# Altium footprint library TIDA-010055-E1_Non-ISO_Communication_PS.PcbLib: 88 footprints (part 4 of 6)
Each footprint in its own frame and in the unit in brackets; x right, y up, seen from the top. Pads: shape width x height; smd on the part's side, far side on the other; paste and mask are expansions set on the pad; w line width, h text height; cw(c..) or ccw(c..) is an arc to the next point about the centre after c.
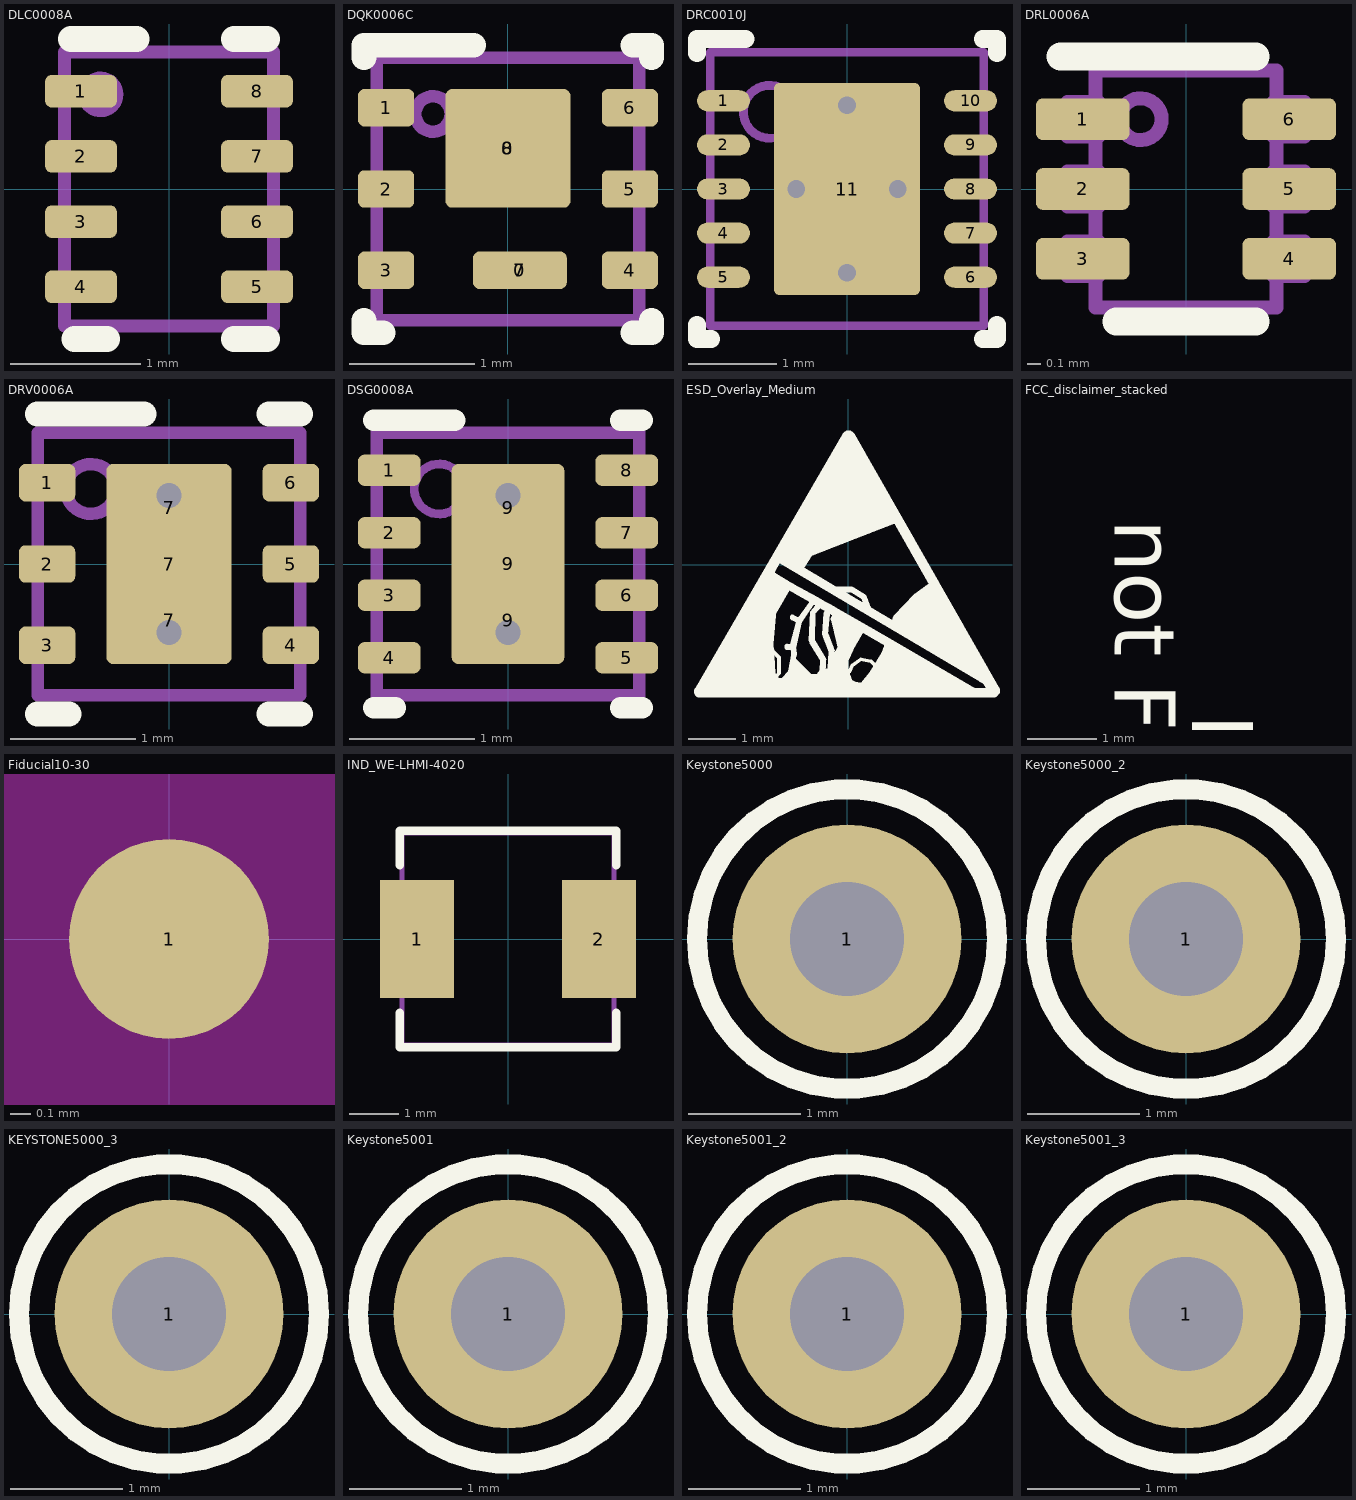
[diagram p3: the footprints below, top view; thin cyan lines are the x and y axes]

## DLC0008A [mm] "QFN-8 (2.0mmX1.5mm)"
height 1
pads (8):
  rrect40% 0.55x0.25 smd: 1(-0.675,0.75) 2(-0.675,0.25) 3(-0.675,-0.25) 4(-0.675,-0.75) 5(0.675,-0.75) 6(0.675,-0.25) 7(0.675,0.25) 8(0.675,0.75)
Top Overlay:
  lines w0.2: -0.75,1.15 -0.25,1.15 ; -0.725,-1.15 -0.475,-1.15 ; 0.5,-1.15 0.75,-1.15 ; 0.5,1.15 0.75,1.15
Mechanical 5:
  circle w0.1: c-0.525,0.725 r0.125
  lines w0.1: -0.8,-1.05 -0.8,1.05 0.8,1.05 0.8,-1.05 -0.8,-1.05
  text ".Designator" at 0.702,-3.338 h0.64
3D body: height 1, standoff 0, extent -0.799,-1.049 0.799,1.049
3D body: height 1.02, standoff 0.5, extent -0.549,0.601 -0.301,0.849

## DQK0006C [mm] "WSON"
height 0.8
pads (10):
  rrect50% 0.9x0.86 on Top Paste: 0(0,0.325)
  rrect50% 0.7x0.29 on Top Paste: 0(0.095,-0.65)
  rrect33% 0.45x0.3 smd: 1(-0.975,0.65) 2(-0.975,0) 3(-0.975,-0.65) 4(0.975,-0.65) 5(0.975,0) 6(0.975,0.65)
  rrect33% 0.75x0.3 smd paste-0.15: 7(0.095,-0.65)
  rrect11% 1x0.95 smd paste-0.5: 8(0,0.325)
Top Overlay:
  lines w0.2: -1.15,-1.05 -1.15,-1.15 -1,-1.15 ; -1.15,1.05 -1.15,1.15 -0.275,1.15 ; 1,-1.15 1.15,-1.15 1.15,-1.05 ; 1,1.15 1.15,1.15 1.15,1.05
Mechanical 5:
  circle w0.1: c-0.6,0.6 r0.141
  lines w0.1: -1.05,-1.05 1.05,-1.05 1.05,1.05 -1.05,1.05 -1.05,-1.05
  text ".Designator" at -0.524,-0.406 h0.64
3D body "DQK0006C.stp": height 0.82, standoff 0, extent -1,-1 1,1

## DRC0010J [mm] "SON, 10-Leads, Body 3x3mm, Pitch 0.5mm, Thermal Pad 2.4x1.65mm, TI Recommended"
height 1
pads (11):
  rrect100% 0.6x0.24 smd: 1(-1.4,1) 2(-1.4,0.5) 3(-1.4,0) 4(-1.4,-0.5) 5(-1.4,-1) 6(1.4,-1) 7(1.4,-0.5) 8(1.4,0) 9(1.4,0.5) 10(1.4,1)
  rrect6% 1.65x2.4 smd paste-0.825: 11(0,0)
via 0,-0.95 diameter 0.5 hole 0.2
via -0.575,0 diameter 0.5 hole 0.2
via 0,0.95 diameter 0.5 hole 0.2
via 0.575,0 diameter 0.5 hole 0.2
Top Overlay:
  lines w0.2: -1.7,-1.54 -1.7,-1.7 -1.54,-1.7 ; -1.7,1.54 -1.7,1.7 -1.15,1.7 ; 1.54,-1.7 1.7,-1.7 1.7,-1.54 ; 1.54,1.7 1.7,1.7 1.7,1.54
Top Paste:
  rectangle: -0.75,-1.16 0.75,-0.1
  rectangle: -0.75,0.1 0.75,1.16
Mechanical 5:
  circle w0.1: c-0.875,0.875 r0.3
  lines w0.1: -1.55,-1.55 -1.55,1.55 1.55,1.55 1.55,-1.55 -1.55,-1.55
  text ".Designator" at 0.129,0.544 h0.64
3D body "DRC0010J.stp": height 0.77, standoff 0, extent -1.5,-1.5 1.5,1.5

## DRL0006A [mm] "SOTFL, 6-Flat Leads, Body 1.2x1.6x0.6mm, Pitch 0.5mm, TI recommended"
height 0.6
pads (6):
  rrect33% 0.67x0.3 smd: 1(-0.74,0.5) 2(-0.74,0) 3(-0.74,-0.5) 4(0.74,-0.5) 5(0.74,0) 6(0.74,0.5)
Top Overlay:
  lines w0.2: -0.9,0.95 0.5,0.95 ; -0.5,-0.95 0.5,-0.95
Mechanical 5:
  circle w0.1: c-0.325,0.5 r0.15
  lines w0.1: -0.65,-0.625 -0.65,-0.85 0.65,-0.85 0.65,-0.625 ; -0.65,-0.375 -0.65,-0.125 ; -0.65,0.125 -0.65,0.375 ; -0.65,0.625 -0.65,0.85 0.65,0.85 0.65,0.625 ; 0.65,-0.375 0.65,0.375 ; -0.85,-0.625 -0.627,-0.625 -0.627,-0.375 -0.85,-0.375 -0.85,-0.625 ; -0.85,-0.125 -0.85,0.125 -0.627,0.125 -0.627,-0.125 -0.85,-0.125 ; -0.85,0.375 -0.627,0.375 -0.627,0.625 -0.85,0.625 -0.85,0.375 ; 0.627,-0.625 0.85,-0.625 0.85,-0.375 0.627,-0.375 0.627,-0.625 ; 0.627,-0.125 0.627,0.125 0.85,0.125 0.85,-0.125 0.627,-0.125 ; 0.627,0.375 0.85,0.375 0.85,0.625 0.627,0.625 0.627,0.375
  text ".Designator" at -0.825,1.112 h0.64
3D body "DRL0006A.stp": height 0.61, standoff 0.01, extent -0.8,-0.8 0.8,0.8

## DRV0006A [mm] "SON, 6-Leads, Body 2x2mm, Pitch 0.65mm, Thermal Pad 1.6x1mm, TI Recommended"
height 0.8
pads (9):
  rrect33% 0.45x0.3 smd: 1(-0.975,0.65) 2(-0.975,0) 3(-0.975,-0.65) 4(0.975,-0.65) 5(0.975,0) 6(0.975,0.65)
  rrect50% 1x0.7 on Top Paste: 7(0,-0.45) 7(0,0.45)
  rrect10% 1x1.6 smd paste-0.5: 7(0,0)
via 0,-0.55 diameter 0.5 hole 0.2
via 0,0.55 diameter 0.5 hole 0.2
Top Overlay:
  lines w0.2: -1.05,-1.2 -0.8,-1.2 ; -1.05,1.2 -0.2,1.2 ; 0.8,-1.2 1.05,-1.2 ; 0.8,1.2 1.05,1.2
Mechanical 5:
  circle w0.1: c-0.625,0.6 r0.2
  lines w0.1: -1.05,-1.05 1.05,-1.05 1.05,1.05 -1.05,1.05 -1.05,-1.05
  text ".Designator" at 0.731,0.024 h0.64
3D body: height 0.8, standoff 0, extent -1.05,-1.05 1.05,1.05
3D body: height 0.81, standoff 0.5, extent -0.824,0.401 -0.426,0.799

## DSG0008A [mm] "SON, 8-Leads, Body 2x2mm, Pitch 0.5mm, Thermal Pad 1.6x0.9mm, TI Recommended"
height 0.8
pads (11):
  rrect40% 0.5x0.25 smd: 1(-0.95,0.75) 2(-0.95,0.25) 3(-0.95,-0.25) 4(-0.95,-0.75) 5(0.95,-0.75) 6(0.95,-0.25) 7(0.95,0.25) 8(0.95,0.75)
  rrect50% 0.9x0.7 on Top Paste: 9(0,-0.45) 9(0,0.45)
  rrect11% 0.9x1.6 smd paste-0.45: 9(0,0)
via 0,-0.55 diameter 0.5 hole 0.2
via 0,0.55 diameter 0.5 hole 0.2
Top Overlay:
  lines w0.17: -1.075,-1.15 -0.9,-1.15 ; -1.075,1.15 -0.425,1.15 ; 0.9,-1.15 1.075,-1.15 ; 0.9,1.15 1.075,1.15
Mechanical 5:
  circle w0.07: c-0.55,0.6 r0.2
  lines w0.1: -1.05,-1.05 1.05,-1.05 1.05,1.05 -1.05,1.05 -1.05,-1.05
  text ".Designator" at 0.711,0.079 h0.64
3D body "DSG0008A.stp": height 0.77, standoff 0, extent -1,-1 1,1

## ESD_Overlay_Medium [mm]
height 3
Top Overlay:
  drawing of 6916 lines, arcs and shapes, not listed

## FCC_disclaimer_stacked [mm]
height 3
Top Overlay:
  text "not FCC approved for resale." at 2.154,-34.061 h1.52
  text "For evaluation only;" at 3.277,-36.881 h1.52

## Fiducial10-30 [mm]
height 3
pads (1):
  round 1 smd mask+1: 1(0,0)
Top Layer keep-out:
  circle w1.678: c0,0 r0.75

## IND_WE-LHMI-4020 [mm] "WERTH"
height 2
pads (2):
  rect 1.5x2.4 smd: 1(-1.85,0) 2(1.85,0)
Top Overlay:
  lines w0.17: -2.2,-1.5 -2.2,-2.2 2.2,-2.2 2.2,-1.5 ; -2.2,1.5 -2.2,2.2 2.2,2.2 2.2,1.5
Mechanical 5:
  lines w0.1: -2.155,-2.155 2.155,-2.155 2.155,2.155 -2.155,2.155 -2.155,-2.155
  text ".Designator" at -0.584,-0.254 h0.64
3D body: height 2, standoff 0, extent -2.154,-2.154 2.154,2.154

## Keystone5000 [mil] "For Keystone 500x miniature loop terminals"
height 181.1
pads (1):
  round 80 hole 40: 1(0,0)
Top Overlay:
  circle w7: c0,0 r52.5
Mechanical 5:
  circle w3.94: c0,0 r52.5
  text ".Designator" at -25,125 h25
3D body "Keystone_5000.stp": height 181.97, standoff -118.11, extent -49,-49 49.04,49.24

## Keystone5000_2 [mil]
pads (1):
  round 80 hole 40: 1(0,0)
Top Overlay:
  circle w7: c0,0 r52.5
Mechanical 5:
  circle w3.94: c0,0 r52.5
  text ".Designator" at 44.55,74.25 h25
3D body "Keystone_5000.stp": height 181.97, standoff -118.11, extent -49,-49 49.04,49.24

## KEYSTONE5000_3 [mil]
pads (1):
  round 80 hole 40: 1(0,0)
Top Overlay:
  circle w7: c0,0 r52.5
Mechanical 5:
  circle w3.94: c0,0 r52.5
  text ".Designator" at 98.14,-126.92 h25
3D body "Keystone_5000.stp": height 181.97, standoff -118.11, extent -49,-49 49.04,49.24

## Keystone5001 [mil] "For Keystone 500x miniature loop terminals"
height 181.1
pads (1):
  round 80 hole 40: 1(0,0)
Top Overlay:
  circle w7: c0,0 r52.5
Mechanical 5:
  circle w3.94: c0,0 r52.5
  text ".Designator" at 18.89,-91.52 h25
3D body "Keystone_5001.stp": height 181.97, standoff -118.11, extent -49,-49 49.04,49.24

## Keystone5001_2 [mil]
pads (1):
  round 80 hole 40: 1(0,0)
Top Overlay:
  circle w7: c0,0 r52.5
Mechanical 5:
  circle w3.94: c0,0 r52.5
  text ".Designator" at -132,-23 h25
3D body "Keystone_5001.stp": height 181.97, standoff -118.11, extent -49,-49 49.04,49.24

## Keystone5001_3 [mil]
pads (1):
  round 80 hole 40: 1(0,0)
Top Overlay:
  circle w7: c0,0 r52.5
Mechanical 5:
  circle w3.94: c0,0 r52.5
  text ".Designator" at -57,-140 h25
3D body "Keystone_5001.stp": height 181.97, standoff -118.11, extent -49,-49 49.04,49.24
